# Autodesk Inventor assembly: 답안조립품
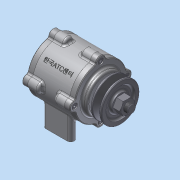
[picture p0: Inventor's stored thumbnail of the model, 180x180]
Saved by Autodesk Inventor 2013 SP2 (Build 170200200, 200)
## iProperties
Created: 2015-03
Part Number: 답안조립품
Document SubType Name: Assembly
Designer: dgall
Author: dgall
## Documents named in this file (11)
- C:\Documents and Settings\dgall\바탕 화면\450305V1029\답안조립품.iam
- C:\Documents and Settings\dgall\바탕 화면\450305V1029\본체.ipt
- C:\Documents and Settings\dgall\바탕 화면\450305V1029\축.ipt
- C:\Documents and Settings\dgall\바탕 화면\450305V1029\V벨트풀리.ipt
- C:\Documents and Settings\dgall\바탕 화면\450305V1029\커버.ipt
- C:\Documents and Settings\dgall\바탕 화면\450305V1029\커버2.ipt
- C:\Documents and Settings\dgall\바탕 화면\450305V1029\베어링 6204.ipt
- C:\Documents and Settings\dgall\바탕 화면\450305V1029\오일실.ipt
- C:\Documents and Settings\dgall\바탕 화면\450305V1029\키(4 x 4 x 12).ipt
- C:\Documents and Settings\dgall\바탕 화면\450305V1029\M 4 x 12.ipt
- C:\Documents and Settings\dgall\바탕 화면\450305V1029\너트 M12x1.25.ipt
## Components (14 placed, 6 different names)
1. 그루브 풀리1:1
2. KS B 2023 6204 - 20 x 47 x 14:1
3. KS B 2023 6204 - 20 x 47 x 14:2
4. KS B 2804 D D - 20 32 8:1
5. KS B 1311 (I) 4 x 4 x 12:1 — 각도:1
6. KS B 1012 클래스 1 일반 - 미터 M12x1.25:1
7. KS B 1003 - 미터 M 4 x 12:1
8. KS B 1003 - 미터 M 4 x 12:2
9. KS B 1003 - 미터 M 4 x 12:3
10. KS B 1003 - 미터 M 4 x 12:4
11. KS B 1003 - 미터 M 4 x 12:5
12. KS B 1003 - 미터 M 4 x 12:6
13. KS B 1003 - 미터 M 4 x 12:7
14. KS B 1003 - 미터 M 4 x 12:8
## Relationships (1: Angle 1)
- 각도:1 [Angle]: KS B 1311 (I) 4 x 4 x 12:1
